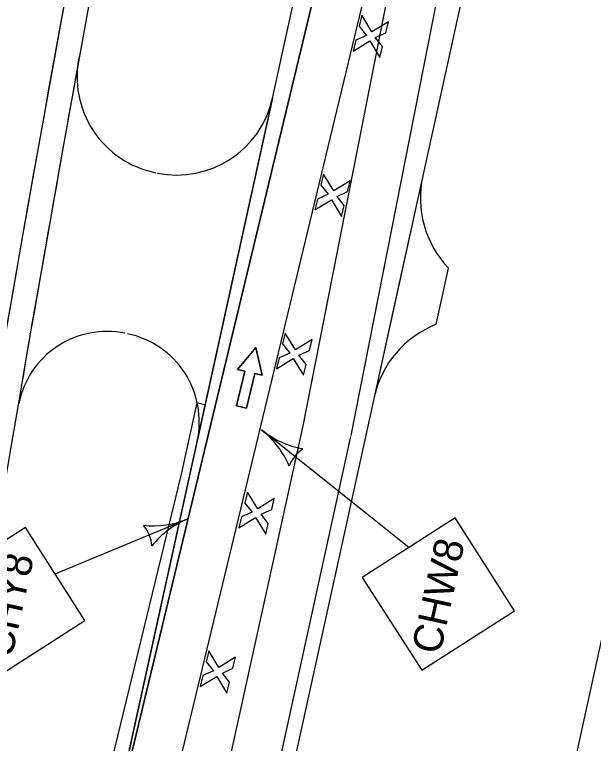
# Model space of a CAD drawing. Extents: x 14104283 to 14121738, y 8635219 to 8671666.
# Drawn here: x 14108061.2 to 14108202.9, y 8640438 to 8640616.4 of the extents above; entities that cross this region are included whole.
import ezdxf

# ---------------------------------------------------------------- set-up
doc = ezdxf.new("R2010")
doc.units = 0
for name, color, linetype in [('Cell', 7, 'Continuous'), ('Default', 7, 'Continuous'), ('dsnPaintExistingBrokenLaneLineWhite', 7, 'Continuous'), ('dsnPaintRemoveEdgeLineWhite', 7, 'Continuous'), ('dsnPaintRemoveEdgeLineYellow', 7, 'Continuous'), ('dsnShadingGranular', 7, 'Continuous'), ('dsnStdLabel', 7, 'Continuous'), ('dsnStgShadingPrevPav', 7, 'Continuous'), ('dsnTapePlaceChannelizingLaneWhite', 7, 'Continuous'), ('dsnTapePlaceChannelizingLaneYellow', 7, 'Continuous'), ('dsnTapeRemoveChannelizingWhite', 7, 'Continuous'), ('dsnTapeRemoveChannelizingYellow', 7, 'Continuous')]:
    doc.layers.add(name, color=color, linetype=linetype)

msp = doc.modelspace()

# ---------------------------------------------------------------- linework, layer by layer
at = {"layer": 'Cell'}
for p, q in [((14108146.18, 8640616.2), (14108145.54, 8640613.53)), ((14108148.67, 8640612.13), (14108146.18, 8640616.2)), ((14108152.74, 8640614.62), (14108148.67, 8640612.13)), ((14108152.1, 8640611.94), (14108152.74, 8640614.62)), ((14108145.54, 8640613.53), (14108147.31, 8640611.3)), ((14108149.5, 8640610.77), (14108152.1, 8640611.94)), ((14108147.31, 8640611.3), (14108144.71, 8640610.13)), ((14108151.27, 8640608.54), (14108149.5, 8640610.77)), ((14108144.71, 8640610.13), (14108144.07, 8640607.46)), ((14108144.07, 8640607.46), (14108148.14, 8640609.94)), ((14108148.14, 8640609.94), (14108150.63, 8640605.87)), ((14108150.63, 8640605.87), (14108151.27, 8640608.54)), ((14108136.82, 8640577.31), (14108136.17, 8640574.63)), ((14108139.31, 8640573.23), (14108136.82, 8640577.31)), ((14108136.17, 8640574.63), (14108137.95, 8640572.4)), ((14108143.38, 8640575.72), (14108139.31, 8640573.23)), ((14108142.73, 8640573.05), (14108143.38, 8640575.72)), ((14108140.13, 8640571.88), (14108142.73, 8640573.05)), ((14108135.35, 8640571.23), (14108134.7, 8640568.56)), ((14108134.7, 8640568.56), (14108138.78, 8640571.05)), ((14108137.95, 8640572.4), (14108135.35, 8640571.23)), ((14108138.78, 8640571.05), (14108141.26, 8640566.97)), ((14108141.91, 8640569.64), (14108140.13, 8640571.88)), ((14108141.26, 8640566.97), (14108141.91, 8640569.64)), ((14108127.47, 8640538.41), (14108126.82, 8640535.74)), ((14108129.95, 8640534.33), (14108127.47, 8640538.41)), ((14108126.82, 8640535.74), (14108128.59, 8640533.51)), ((14108134.03, 8640536.82), (14108129.95, 8640534.33)), ((14108133.38, 8640534.15), (14108134.03, 8640536.82)), ((14108128.59, 8640533.51), (14108126, 8640532.33)), ((14108130.78, 8640532.98), (14108133.38, 8640534.15)), ((14108126, 8640532.33), (14108125.35, 8640529.66)), ((14108125.35, 8640529.66), (14108129.42, 8640532.15)), ((14108129.42, 8640532.15), (14108131.91, 8640528.07)), ((14108132.56, 8640530.75), (14108130.78, 8640532.98)), ((14108131.91, 8640528.07), (14108132.56, 8640530.75)), ((14108118.22, 8640499.49), (14108117.57, 8640496.81)), ((14108120.7, 8640495.41), (14108118.22, 8640499.49)), ((14108124.78, 8640497.9), (14108120.7, 8640495.41)), ((14108124.13, 8640495.23), (14108124.78, 8640497.9)), ((14108117.57, 8640496.81), (14108119.34, 8640494.58)), ((14108119.34, 8640494.58), (14108116.75, 8640493.41)), ((14108121.53, 8640494.05), (14108124.13, 8640495.23)), ((14108116.75, 8640493.41), (14108116.1, 8640490.74)), ((14108116.1, 8640490.74), (14108120.17, 8640493.23)), ((14108120.17, 8640493.23), (14108122.66, 8640489.15)), ((14108123.31, 8640491.82), (14108121.53, 8640494.05)), ((14108122.66, 8640489.15), (14108123.31, 8640491.82)), ((14108108.74, 8640460.61), (14108108.09, 8640457.94)), ((14108111.23, 8640456.54), (14108108.74, 8640460.61)), ((14108115.3, 8640459.03), (14108111.23, 8640456.54)), ((14108114.65, 8640456.35), (14108115.3, 8640459.03)), ((14108108.09, 8640457.94), (14108109.87, 8640455.71)), ((14108109.87, 8640455.71), (14108107.27, 8640454.54)), ((14108112.06, 8640455.18), (14108114.65, 8640456.35)), ((14108113.83, 8640452.95), (14108112.06, 8640455.18)), ((14108107.27, 8640454.54), (14108106.62, 8640451.87)), ((14108106.62, 8640451.87), (14108110.7, 8640454.35)), ((14108110.7, 8640454.35), (14108113.18, 8640450.28)), ((14108113.18, 8640450.28), (14108113.83, 8640452.95))]:
    msp.add_line(p, q, dxfattribs=at)
msp.add_lwpolyline([(14108117.97, 8640520), (14108115.54, 8640520.58), (14108117.56, 8640529.09), (14108115.74, 8640529.53), (14108120.22, 8640534.89), (14108121.82, 8640528.08), (14108120, 8640528.52)], close=True, dxfattribs=at)
msp.add_lwpolyline([(14108120, 8640528.52), (14108121.82, 8640528.08), (14108120.22, 8640534.89), (14108115.74, 8640529.53), (14108117.56, 8640529.09), (14108115.54, 8640520.58), (14108117.97, 8640520), (14108120, 8640528.52)], dxfattribs=at)
at = {"layer": 'Default'}
for p, q in [((14108151.72, 8640692.57), (14108081.5, 8640400.87)), ((14108093.19, 8640398.18), (14108163.38, 8640689.76))]:
    msp.add_line(p, q, dxfattribs=at)
for centre, radius, start, end in [((14117394.14, 8638857.08), 9512, 167.610212, 171.325989), ((14117394.14, 8638857.08), 9500, 167.610212, 171.325989), ((14117502.5, 8638839.63), 9621.75, 168.048489, 169.460498)]:
    msp.add_arc(centre, radius, start, end, dxfattribs=at)
at = {"layer": 'dsnPaintExistingBrokenLaneLineWhite'}
msp.add_arc((14117394.14, 8638857.08), 9500, 167.610212, 171.325989, dxfattribs=at)
at = {"layer": 'dsnPaintRemoveEdgeLineWhite'}
msp.add_line((14108117.15, 8640393.04), (14108143.52, 8640513.09), dxfattribs=at)
at = {"layer": 'dsnPaintRemoveEdgeLineYellow'}
msp.add_line((14108105.43, 8640395.62), (14108131.8, 8640515.67), dxfattribs=at)
at = {"layer": 'dsnShadingGranular'}
for p, q in [((14108161.12, 8640576.89), (14108155.11, 8640549.54)), ((14108155.11, 8640549.54), (14108149.21, 8640522.69))]:
    msp.add_line(p, q, dxfattribs=at)
at = {"layer": 'dsnStdLabel'}
for p, q in [((14108185.98, 8640377.23), (14108250.34, 8640670.22)), ((14108157.68, 8640485.88), (14108121.67, 8640514.71)), ((14108071.14, 8640479.45), (14108103.75, 8640492.99))]:
    msp.add_line(p, q, dxfattribs=at)
for points in [[(14108160.86, 8640455.86), (14108183.6, 8640470.41), (14108169.05, 8640493.15), (14108146.31, 8640478.6)], [(14108055.67, 8640453.53), (14108078.42, 8640468.08), (14108063.87, 8640490.82), (14108041.12, 8640476.27)]]:
    msp.add_lwpolyline(points, close=True, dxfattribs=at)
for centre, radius, start, end in [((14108107.33, 8640496.79), 22.95, 23.2472, 51.3185), ((14108136.01, 8640532.62), 22.95, 231.3184, 259.3896), ((14108136.69, 8640502.68), 8.86, 123.5842, 159.0526), ((14108094.95, 8640514.19), 22.95, 264.4795, 292.5508), ((14108112.56, 8640471.8), 22.95, 112.5506, 140.6219), ((14108085.98, 8640485.61), 8.86, 4.8164, 40.2849)]:
    msp.add_arc(centre, radius, start, end, dxfattribs=at)
at = {"layer": 'dsnStgShadingPrevPav'}
for p, q in [((14108124.35, 8640595.95), (14108105.9, 8640511.97)), ((14108161.12, 8640576.89), (14108155.11, 8640549.54)), ((14108165.86, 8640547.18), (14108167.42, 8640554.3)), ((14108155.11, 8640549.54), (14108149.21, 8640522.69)), ((14108164.4, 8640540.56), (14108165.86, 8640547.18))]:
    msp.add_line(p, q, dxfattribs=at)
for points in [[(14108081.5, 8640400.87), (14108123.34, 8640591.33), (14108126.55, 8640605.98), (14108216.67, 8641016.2), (14108268.16, 8641250.61), (14108382.95, 8641773.15), (14108422.02, 8641764.57), (14108309.38, 8641251.8), (14108270.22, 8641073.55), (14108265.93, 8641054.01), (14108255.74, 8641007.62), (14108202.1, 8640763.44), (14108120.56, 8640392.29)], [(14108077.26, 8640401.8), (14108102.07, 8640503.86), (14108105.91, 8640521.35), (14108107.87, 8640520.92), (14108081.5, 8640400.87)]]:
    msp.add_lwpolyline(points, close=True, dxfattribs=at)
for centre, radius, start, end in [((14117407.82, 8638919.35), 9488, 167.610212, 172.222077), ((14117407.82, 8638919.35), 9482, 167.610212, 172.222077), ((14117407.82, 8638919.35), 9488, 169.413861, 172.222077), ((14108100.48, 8640601.19), 24, 168.2241, 258.4908), ((14117407.82, 8638919.35), 9482, 169.768725, 170.278029), ((14108100.91, 8640601.1), 24, 258.4908, 347.6102), ((14108185.53, 8640571.53), 25, 167.6114, 223.5657), ((14108173.63, 8640517.32), 25, 111.6547, 167.6089), ((14108083.79, 8640516.82), 22, 78.4908, 168.7454), ((14108084.41, 8640516.69), 22, 347.6102, 78.4908)]:
    msp.add_arc(centre, radius, start, end, dxfattribs=at)
at = {"layer": 'dsnTapePlaceChannelizingLaneWhite'}
msp.add_line((14108093.19, 8640398.18), (14108163.38, 8640689.76), dxfattribs=at)
at = {"layer": 'dsnTapePlaceChannelizingLaneYellow'}
msp.add_line((14108081.5, 8640400.87), (14108151.72, 8640692.57), dxfattribs=at)
at = {"layer": 'dsnTapeRemoveChannelizingWhite'}
msp.add_line((14108143.57, 8640513.35), (14108201.59, 8640807.75), dxfattribs=at)
at = {"layer": 'dsnTapeRemoveChannelizingYellow'}
msp.add_line((14108131.8, 8640515.67), (14108189.82, 8640810.08), dxfattribs=at)

# ---------------------------------------------------------------- texts
at = {"layer": 'dsnStdLabel'}
for s, p in [('CHW8', (14108165.34, 8640459.49)), ('CHY8', (14108060.45, 8640458.52))]:
    msp.add_text(s, height=7.2, rotation=77.6078, dxfattribs=at).set_placement(p)

doc.saveas('drawing.dxf')
